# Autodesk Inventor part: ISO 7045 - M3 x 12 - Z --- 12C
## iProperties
Created: 2011-01
Part Number: ISO 7045 - M3 x 12 - Z --- 12C
Document SubType Name: Modeling
Designer: eric
Density: 1 g/cm^3
Mass: 0.129772 g
Surface Area: 2.00825 cm^2
Volume: 0.129772 cm^3
Author: eric
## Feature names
1. Base1
